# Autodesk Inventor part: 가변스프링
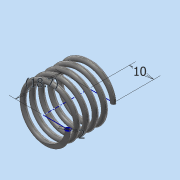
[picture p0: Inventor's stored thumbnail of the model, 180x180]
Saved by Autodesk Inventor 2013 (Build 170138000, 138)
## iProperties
Created: 2019-01
Part Number: 가변스프링
Material: 스테인리스강
Document SubType Name: Modeling
Designer: dgall
Density: 8.08 g/cm^3
Mass: 7.79362 g
Surface Area: 19.6283 cm^2
Volume: 0.964557 cm^3
Author: dgall
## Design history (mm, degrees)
sketch "스케치1"
  geometry: L1 (10, 18.7)-(0, 18.7); L2 (0, 18.7)-(0, 0); L3 (0, 0)-(10, 0); C1 r 1 at (10, 0)
  constraints: 6 end point, 1 centre point, 1 coincident, 1 horizontal, 1 parallel, 1 vertical, 1 vertical alignment
  dimensions: "d0" = 10 distance of L1.start L1.end; "d2" = 18.7 distance of L1.end L2.end (derived); "d3" = 2 diameter of C1
feature "코일1" sketch "스케치1" pitch "d4" = 10; turns "d6" = 5; dims "d5" = 18.7 (= d2), "d7" = 0, angle "d8" = 90 deg, angle "d9" = 90 deg, "d10" = 0, "d11" = 0
feature "분할1"
node "작업 평면1"
feature "분할2"
node "솔리드1"
other parameters: "d12" = 0
